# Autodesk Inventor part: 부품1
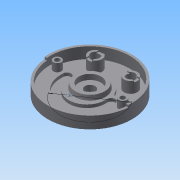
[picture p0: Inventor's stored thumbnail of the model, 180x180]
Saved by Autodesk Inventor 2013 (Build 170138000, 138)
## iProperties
Created: 2015-05
Part Number: 부품1
Material: 일반
Document SubType Name: Modeling
Designer: Administrator
Density: 1 g/cm^3
Author: Administrator
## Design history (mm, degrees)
sketch "스케치1"
  geometry: C1 r 95 at (0, 0); 1 further point
  constraints: 1 centre point, 1 coincident
  dimensions: "d0" = 190 diameter of C1
extrude "돌출1" new body sketch "스케치1" distance "d2" = 32; taper "d3" = 0 deg
sketch "스케치2"
  geometry: C1 r 95 at (0, 0) reference; C2 r 90 at (0, 0)
  constraints: 1 centre point, 1 coincident
  dimensions: "d4" = 180 diameter of C2
extrude "돌출2" cut sketch "스케치2" distance "d6" = 18; taper "d7" = 0 deg
sketch "스케치3"
  geometry: L1 (-89.196, 12)-(89.196, 12); L2 (-82.153, -7)-(80.893, -7); L3 (0, 0)-(0, -95); L4 (-82.153, -2)-(80.893, -2); L5 (59, -7)-(59, -2); L6 (41, -7)-(41, -2); L7 (-41, -7)-(-41, -2); L8 (-59, -7)-(-59, -2); A1 r 90 centre (0, 0) between (89.196, 12) and (-89.196, 12); A2 r 59 centre (0, -7) between (-59, -7) and (59, -7); A3 r 41 centre (0, -7) between (-41, -7) and (41, -7); A4 r 9 centre (50, -2) between (59, -2) and (41, -2); A5 r 9 centre (-50, -2) between (-41, -2) and (-59, -2); 3 further points
  constraints: 16 end point, 10 point on circle, 5 centre point, 5 point on line, 3 parallel, 3 symmetric about line, 3 tangent, 2 coincident, 2 perpendicular, 1 horizontal, 1 horizontal alignment, 1 midpoint, 1 vertical alignment, 2 other
  dimensions: "d10" = 90 radius of A1; "d11" = 12 distance from line of L1 point (0, 0); "d12" = 19 distance between parallel lines of L2 L1; "d13" = 59 radius of A2; "d14" = 41 radius of A3; "d15" = 5 distance between parallel lines of L4 L2; "d16" = 18 diameter of A4; "d17" = 5 distance of L8.start L8.end; "d18" = 5 distance of L7.start L7.end
extrude "돌출3" cut sketch "스케치3" distance "d19" = 7; taper "d20" = 0 deg
sketch "스케치4"
  geometry: L1 (89.196, 12)-(-89.196, 12) reference; A1 r 90 centre (0, 0) between (89.196, 12) and (-89.196, 12) reference; A2 r 42 centre (0, 0) between (40.249, 12) and (-40.249, 12)
  constraints: 2 point on circle, 2 point on line, 1 centre point, 1 coincident
  dimensions: "d21" = 84 diameter of A2
extrude "돌출4" join sketch "스케치4" distance "d23" = 7; taper "d24" = 0 deg
sketch "스케치5"
  geometry: C1 r 35 at (0, 0); A1 r 90 centre (0, 0) between (-89.196, 12) and (89.196, 12) reference
  constraints: 1 centre point, 1 coincident
  dimensions: "d25" = 70 diameter of C1
extrude "돌출5" join sketch "스케치5" distance "d26" = 10; taper "d27" = -10 deg
sketch "스케치6"
  geometry: C1 r 95 at (0, 0) reference; C2 r 25 at (0, 0)
  constraints: 1 centre point, 1 coincident
  dimensions: "d28" = 50 diameter of C2
extrude "돌출6" join sketch "스케치6" distance "d29" = 12; taper "d30" = -15 deg
hole "구멍1" diameter "d33" = 23; stored, may be unused: countersink angle "d37" = 90 deg, drill point angle "d39" = 0 deg; dims "d34" = 6, "d35" = 50, "d36" = 12, "d38" = 15, "d40" = 10, "d41" = 10
sketch "스케치7"
  geometry: L1 (-40.249, 12)-(-89.196, 12) reference; L2 (0, 90)-(0, 0); C1 r 15 at (-40, 52); C2 r 15 at (40, 52); A1 r 42 centre (0, 0) between (40.249, 12) and (-40.249, 12) reference; A2 r 90 centre (0, 0) between (89.196, 12) and (-89.196, 12) reference
  constraints: 2 centre point, 2 end point, 1 perpendicular, 1 point on circle, 1 symmetric about line, 1 other
  dimensions: "d42" = 30 diameter of C1; "d43" = 80 distance of C2.centre C1.centre; "d44" = 52 vertical distance of C2.centre A1.centre
extrude "돌출7" join sketch "스케치7" distance "d45" = 25; taper "d46" = 0 deg
hole "구멍2" diameter "d49" = 20; stored, may be unused: countersink angle "d53" = 90 deg, drill point angle "d55" = 0 deg; dims "d47" = 10, "d48" = 10, "d50" = 6, "d51" = 4, "d52" = 2, "d54" = 15
hole "구멍3" diameter "d58" = 20; stored, may be unused: countersink angle "d62" = 90 deg, drill point angle "d64" = 0 deg; dims "d56" = 10, "d57" = 10, "d59" = 6, "d60" = 4, "d61" = 2, "d63" = 15
sketch "스케치8"
  geometry: L1 (-6, 17.94)-(6, 17.94); L2 (6, 17.94)-(6, -17.94); L3 (6, -17.94)-(-6, -17.94); L4 (-6, -17.94)-(-6, 17.94); C1 r 10 at (0, 0) reference; 3 further points
  constraints: 8 end point, 2 midpoint, 2 parallel, 1 horizontal, 1 horizontal alignment, 1 perpendicular, 1 vertical alignment
  dimensions: "d65" = 12 distance between parallel lines of L2 L4; "d67" = 35.87996 distance between parallel lines of L3 L1
extrude "돌출8" cut sketch "스케치8" distance "d68" = 3; taper "d69" = 0 deg
sketch "스케치9"
  geometry: L1 (-18.483, 6)-(18.483, 6); L2 (18.483, 6)-(18.483, -6); L3 (18.483, -6)-(-18.483, -6); L4 (-18.483, -6)-(-18.483, 6); C1 r 10 at (0, 0) reference; 3 further points
  constraints: 8 end point, 2 midpoint, 2 parallel, 1 horizontal, 1 horizontal alignment, 1 perpendicular, 1 vertical alignment
  dimensions: "d70" = 12 distance between parallel lines of L3 L1; "d72" = 36.96686 distance between parallel lines of L2 L4
extrude "돌출9" cut sketch "스케치9" distance "d73" = 3; taper "d74" = 0 deg
sketch "스케치10"
  geometry: L1 (0, 0)-(0, -90); C1 r 35 at (0, 0) reference; C2 r 95 at (0, 0) reference; C3 r 9 at (-74, 0); C4 r 9 at (74, 0); A1 r 90 centre (0, 0) between (-89.196, 12) and (89.196, 12) reference
  constraints: 2 centre point, 2 end point, 1 horizontal alignment, 1 point on circle, 1 symmetric about line, 1 other
  dimensions: "d75" = 18 diameter of C3; "d76" = 148 distance of C4.centre C3.centre
extrude "돌출10" join sketch "스케치10" distance "d77" = 18; taper "d78" = 0 deg
sketch "스케치11"
  geometry: C1 r 9 at (-74, 0) reference; C2 r 9 at (74, 0) reference; C3 r 9 at (-74, 0) reference; 2 further points
  constraints: 2 coincident
hole "구멍4" sketch "스케치11" at (-74, 0), (74, 0) diameter "d79" = 11; stored, may be unused: countersink angle "d83" = 90 deg, drill point angle "d85" = 0 deg; dims "d80" = 6, "d81" = 18, "d82" = 11, "d84" = 15
sketch "스케치12"
  geometry: L1 (0, 0)-(-89.658, -7.844); L2 (0, 0)-(89.658, -7.844); L3 (-90, 0)-(90, 0); L4 (89.658, -7.844)-(94.638, -8.28); L5 (-89.658, -7.844)-(-94.638, -8.28); A1 r 90 centre (0, 0) between (-90, 0) and (89.196, 12) reference; A2 r 95 centre (0, 0) between (-94.638, -8.28) and (94.638, -8.28) reference; A3 r 90 centre (0, 0) between (-89.196, 12) and (89.196, 12) reference; A4 r 95 centre (0, 0) between (-94.638, -8.28) and (94.638, -8.28); A5 r 90 centre (0, 0) between (89.658, -7.844) and (-89.658, -7.844)
  constraints: 10 end point, 9 point on circle, 2 centre point, 2 coincident, 1 concentric, 1 horizontal, 1 midpoint
  dimensions: "d86" = 180 diameter of A5; "d88" = 5 deg angle of L1 L3; "d90" = 5 deg angle of L2 L3; "d92" = 5 deg angle of L5 L3; "d94" = 5 deg angle of L4 L3
extrude "돌출11" cut sketch "스케치12" distance "d96" = 5; taper "d97" = 0 deg
fillet "모깎기1" dims "d98" = 10
sketch "스케치13"
  geometry: L1 (0, 0)-(0, -72); L2 (0, 0)-(-36.062, -36.062); L3 (0, 0)-(36.062, -36.062); L4 (-36.062, -36.062)-(-50.912, -50.912); L5 (36.062, -36.062)-(50.912, -50.912); C1 r 25 at (0, 0) reference; C2 r 11.5 at (0, 0) reference; A1 r 51 centre (0, 0) between (-36.062, -36.062) and (36.062, -36.062); A2 r 72 centre (0, 0) between (71.48, -8.64) and (-50.912, -50.912); A3 r 72 centre (0, 0) between (50.912, -50.912) and (71.48, -8.64); A4 r 72 centre (0, 0) between (-50.912, -50.912) and (50.912, -50.912); A5 r 51 centre (0, 0) between (36.062, -36.062) and (-36.062, -36.062); 1 further point
  constraints: 12 point on circle, 10 end point, 5 centre point, 2 coincident, 1 symmetric about line, 1 vertical, 2 other
  dimensions: "d100" = 51 radius of A1; "d101" = 72 radius of A2; "d102" = 90 deg angle of L3 L2; "d103" = 21 distance of L3.end L5.end; "d105" = 14.84924 horizontal distance of L2.end L4.end
extrude "돌출12" join sketch "스케치13" distance "d106" = 5; taper "d107" = 0 deg
fillet "모깎기2" dims "d108" = 5
fillet "모깎기3" dims "d109" = 3
sketch "스케치15"
  geometry: L1 (37.378, -41.502)-(45.182, -49.306) reference; L2 (-45.182, -49.306)-(-37.378, -41.502) reference; L3 (0, 0)-(-48.083, -48.083); L4 (0, 0)-(48.083, -48.083); A1 r 68 centre (0, 0) between (-48.083, -48.083) and (-45.74, -50.317); A2 r 68 centre (0, 0) between (48.083, -48.083) and (-48.083, -48.083); A3 r 68 centre (0, 0) between (-45.74, -50.317) and (45.74, -50.317); A4 r 68 centre (0, 0) between (45.74, -50.317) and (48.083, -48.083); 5 further points
  constraints: 8 point on circle, 4 centre point, 4 end point, 2 horizontal alignment, 1 coincident, 1 parallel, 1 perpendicular, 7 other
  dimensions: "d111" = 136 diameter of A1
node "솔리드1"
